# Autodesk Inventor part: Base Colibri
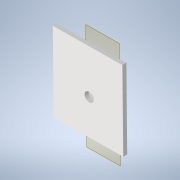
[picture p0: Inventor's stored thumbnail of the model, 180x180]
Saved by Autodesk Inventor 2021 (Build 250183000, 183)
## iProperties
Created: 2021-03
Part Number: Base Colibri
Material: Genérico
Document SubType Name: Modeling
Designer: ATOUZA
Density: 1 g/cm^3
Appearance: Valor por defecto
Author: ATOUZA
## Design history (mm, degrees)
node "Plano de trabajo1"
sketch "Boceto1"
  geometry: L1 (-63.941, -55)-(33.059, -55); L2 (33.059, -55)-(32.926, 55.056); L3 (32.926, 55.056)-(-64.074, 54.94); L4 (-64.074, 54.94)-(-63.941, -55); L5 (22.995, -1.756)-(23.038, -37.956) reference; L6 (26.995, -1.751)-(22.995, -1.756) reference; L7 (26.989, 3.049)-(26.995, -1.751) reference; L8 (53.989, 3.082)-(26.989, 3.049) reference; L9 (53.938, 45.082)-(53.989, 3.082) reference; L10 (-47.062, 44.96)-(53.938, 45.082) reference; L11 (-53.962, -38.048)-(-54.053, 37.952) reference; L12 (16.047, -44.964)-(-46.953, -45.04) reference; L13 (-44.333, 132.372)-(-43.877, -247.628); L14 (28.95, -246.94)-(11.45, -246.961) reference; L15 (15.667, 132.444)-(16.123, -247.556); C1 r 6.4 at (-13.9, -6.2) reference; C2 r 2.25 at (-45.419, -31.764) reference; C3 r 2.25 at (-13.956, 40.7) reference; C4 r 2.25 at (17.681, -31.689) reference; C5 r 6.4 at (-13.9, -6.2) reference; C6 r 6.4 at (-13.9, -6.2); C7 r 2.25 at (-13.956, 40.7); C8 r 2.25 at (17.681, -31.689); C9 r 2.25 at (-45.419, -31.764); C10 r 2 at (-44.114, -50.036); C11 r 2 at (15.766, 50.036); C12 r 2 at (-44.234, 49.964); C13 r 2 at (15.886, -49.964); A1 r 7 centre (16.038, -37.964) between (16.047, -44.964) and (23.038, -37.956) reference; A2 r 7 centre (-47.053, 37.96) between (-47.062, 44.96) and (-54.053, 37.952) reference; A3 r 7 centre (-46.962, -38.04) between (-53.962, -38.048) and (-46.953, -45.04) reference; A4 r 2 centre (55.667, 132.492) between (56.622, 130.735) and (56.618, 134.251) reference; A5 r 2 centre (35.667, 132.468) between (36.622, 130.711) and (36.618, 134.227) reference; A6 r 2 centre (15.667, 132.444) between (16.622, 130.687) and (16.618, 134.203) reference; A7 r 2 centre (-4.333, 132.42) between (-3.378, 130.663) and (-3.382, 134.179) reference; A8 r 2 centre (-24.333, 132.396) between (-23.378, 130.639) and (-23.382, 134.155) reference; A9 r 2 centre (-44.333, 132.372) between (-43.378, 130.615) and (-43.382, 134.131) reference; A10 r 2 centre (-64.333, 132.348) between (-63.378, 130.591) and (-63.382, 134.107) reference; A11 r 2 centre (-84.333, 132.324) between (-83.378, 130.567) and (-83.382, 134.083) reference; A12 r 2 centre (-43.877, -247.628) between (-42.921, -249.385) and (-42.925, -245.868) reference; A13 r 2 centre (-63.877, -247.652) between (-62.921, -249.409) and (-62.925, -245.892) reference; A14 r 2 centre (-83.877, -247.676) between (-82.921, -249.433) and (-82.925, -245.917) reference; A15 r 2 centre (16.123, -247.556) between (17.079, -249.312) and (17.075, -245.796) reference; 2 further points
  constraints: 12 end point, 8 centre point, 5 point on line, 4 coincident, 4 concentric, 1 equal length, 1 horizontal, 1 parallel, 1 other
  dimensions: "d0" = 10 distance between parallel lines of L2 L5; "d1" = 10 distance between parallel lines of L3 L10; "d3" = 10 dimension on L1 L12; "d4" = 10 distance between parallel lines of L4 L11; "d7" = 4 diameter of C10; "d9" = 4 diameter of C11; "d10" = 4 diameter of C12; "d11" = 4 diameter of C13; "d12" = 5 distance from line of L12 C10.centre; "d13" = 5 distance from line of L12 C13.centre; "d14" = 5 distance from line of L10 C12.centre; "d15" = 5 distance from line of L10 C11.centre
extrude "Extrusión1" new body sketch "Boceto1" distance "d5" = 5.5; taper "d6" = 0 deg
fillet "Empalme1" dims "d16" = 4
node "Sólido1"
node "Referencia1"
node "Referencia2"
node "Referencia3"
node "Referencia4"
node "Referencia5"
node "Referencia6"
node "Referencia7"
node "Referencia8"
node "Referencia9"
node "Referencia10"
node "Referencia11"
node "Referencia12"
node "Referencia13"
node "Referencia15"
node "Referencia16"
